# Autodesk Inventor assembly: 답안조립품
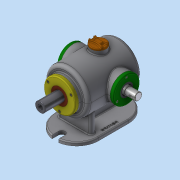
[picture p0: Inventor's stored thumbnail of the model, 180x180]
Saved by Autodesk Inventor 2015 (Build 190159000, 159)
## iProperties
Created: 2018-02
Part Number: 답안조립품
Document SubType Name: Assembly
Designer: SCD-A03
Author: SCD-A03
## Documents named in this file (16)
- C:\Users\SCD-A03\Desktop\380208V1004\답안조립품.iam
- C:\Users\SCD-A03\Desktop\380208V1004\본체.ipt
- C:\Users\SCD-A03\Desktop\380208V1004\가변스프링.ipt
- C:\Users\SCD-A03\Desktop\380208V1004\베어링 6205.ipt
- 베어링 6205.ipt
- C:\Users\SCD-A03\Desktop\380208V1004\본체커버.ipt
- C:\Users\SCD-A03\Desktop\380208V1004\볼트 M4.ipt
- C:\Users\SCD-A03\Desktop\380208V1004\부시.ipt
- C:\Users\SCD-A03\Desktop\380208V1004\상부 캡.ipt
- C:\Users\SCD-A03\Desktop\380208V1004\슬라이드 커버.ipt
- C:\Users\SCD-A03\Desktop\380208V1004\슬라이드.ipt
- C:\Users\SCD-A03\Desktop\380208V1004\오일실.ipt
- 오일실.ipt
- C:\Users\SCD-A03\Desktop\380208V1004\축 커버-1.ipt
- C:\Users\SCD-A03\Desktop\380208V1004\축 커버-2.ipt
- C:\Users\SCD-A03\Desktop\380208V1004\편심축.ipt
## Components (1 placed, 1 different names)
1. 가변스프링:1
